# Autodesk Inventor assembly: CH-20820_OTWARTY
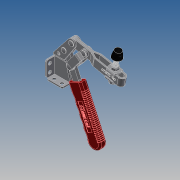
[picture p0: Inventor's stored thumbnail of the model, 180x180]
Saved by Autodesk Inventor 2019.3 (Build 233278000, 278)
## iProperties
Company: Î¢ÈíÖÐ¹ú
Created: 2011-12
Part Number: CH-20820_OTWARTY
Material: Ogólny
Description: STEP AP203
Document SubType Name: Assembly
Designer: CADENGINEERING4
Sending System: SolidWorks 2010
Preprocessor: SwSTEP 2.0
Title: CH-20820.STEP
Author: Î¢ÈíÓÃ»§
Revision Number: ÈÎºÎ
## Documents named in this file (10)
- E:\STRONA\Horizontal toggle clamp\CH-20820\CH-20820_OTWARTY.iam
- E:\STRONA\Horizontal toggle clamp\CH-20820\20820-02.ipt
- E:\STRONA\Horizontal toggle clamp\CH-20820\20820-06.ipt
- E:\STRONA\Horizontal toggle clamp\CH-20820\56212.ipt
- E:\STRONA\Horizontal toggle clamp\CH-20820\20820-03.ipt
- E:\STRONA\Horizontal toggle clamp\CH-20820\FW516.ipt
- E:\STRONA\Horizontal toggle clamp\CH-20820\20820-04.ipt
- E:\STRONA\Horizontal toggle clamp\CH-20820\CH-20820-05.ipt
- E:\STRONA\Horizontal toggle clamp\CH-20820\56212-02.ipt
- E:\STRONA\Horizontal toggle clamp\CH-20820\20820-01.ipt
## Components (15 placed, 15 different names)
1. 20820-02_1 — Zestawiające:1, Zestawiające:4, Zestawiające:6, Zestawiające:9, Zestawiające:24, Zestawiające:25, Zestawiające:28
2. 20820-06_2 — Zestawiające:22, Zestawiające:23
3. 56212_3 — Równoległe:1, Zestawiające:2, Zestawiające:5, Zestawiające:7, Zestawiające:9
4. 20820-06_4 — Zestawiające:28, Zestawiające:29, Zestawiające:30
5. 20820-03_5 — Zestawiające:10, Zestawiające:11, Zestawiające:12, Zestawiające:13, Zestawiające:14, Zestawiające:17, Zestawiające:18, Zestawiające:19, Zestawiające:20
6. FW516_6 — Równoległe:2, Zestawiające:5, Zestawiające:6, Zestawiające:8
7. 20820-04_7 — Zestawiające:19, Zestawiające:20, Zestawiające:21, Zestawiające:22, Zestawiające:23, Zestawiające:24, Zestawiające:25, Zestawiające:26, Zestawiające:27
8. CH-20820-05_8 — Zestawiające:10, Zestawiające:11, Zestawiające:12, Zestawiające:31
9. 56212-02_9 — Równoległe:1, Zestawiające:3
10. 20820-01_10 — Zestawiające:13, Zestawiające:14, Zestawiające:15, Zestawiające:16, Zestawiające:29, Zestawiające:30, Zestawiające:31
11. 20820-06_11 — Zestawiające:15, Zestawiające:16
12. 20820-06_12 — Zestawiające:26, Zestawiające:27
13. FW516_13 — Równoległe:2, Zestawiające:1, Zestawiające:2, Zestawiające:3, Zestawiające:4
14. 56212-02_14 — Zestawiające:7, Zestawiające:8
15. 20820-04_15 — Zestawiające:17, Zestawiające:18, Zestawiające:21
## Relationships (33: Mate 31, Flush 2)
- Równoległe:1 [Flush]: 56212_3 ↔ 56212-02_9
- Równoległe:2 [Flush]: FW516_6 ↔ FW516_13
- Zestawiające:1 [Mate]: 20820-02_1 ↔ FW516_13
- Zestawiające:2 [Mate]: 56212_3 ↔ FW516_13
- Zestawiające:3 [Mate]: 56212-02_9 ↔ FW516_13
- Zestawiające:4 [Mate]: 20820-02_1 ↔ FW516_13
- Zestawiające:5 [Mate]: 56212_3 ↔ FW516_6
- Zestawiające:6 [Mate]: 20820-02_1 ↔ FW516_6
- Zestawiające:7 [Mate]: 56212_3 ↔ 56212-02_14
- Zestawiające:8 [Mate]: FW516_6 ↔ 56212-02_14
- Zestawiające:9 [Mate]: 20820-02_1 ↔ 56212_3
- Zestawiające:10 [Mate]: 20820-03_5 ↔ CH-20820-05_8
- Zestawiające:11 [Mate]: 20820-03_5 ↔ CH-20820-05_8
- Zestawiające:12 [Mate]: 20820-03_5 ↔ CH-20820-05_8
- Zestawiające:13 [Mate]: 20820-03_5 ↔ 20820-01_10
- Zestawiające:14 [Mate]: 20820-03_5 ↔ 20820-01_10
- Zestawiające:15 [Mate]: 20820-01_10 ↔ 20820-06_11
- Zestawiające:16 [Mate]: 20820-01_10 ↔ 20820-06_11
- Zestawiające:17 [Mate]: 20820-03_5 ↔ 20820-04_15
- Zestawiające:18 [Mate]: 20820-03_5 ↔ 20820-04_15
- Zestawiające:19 [Mate]: 20820-03_5 ↔ 20820-04_7
- Zestawiające:20 [Mate]: 20820-03_5 ↔ 20820-04_7
- Zestawiające:21 [Mate]: 20820-04_7 ↔ 20820-04_15
- Zestawiające:22 [Mate]: 20820-06_2 ↔ 20820-04_7
- Zestawiające:23 [Mate]: 20820-06_2 ↔ 20820-04_7
- Zestawiające:24 [Mate]: 20820-02_1 ↔ 20820-04_7
- Zestawiające:25 [Mate]: 20820-02_1 ↔ 20820-04_7
- Zestawiające:26 [Mate]: 20820-04_7 ↔ 20820-06_12
- Zestawiające:27 [Mate]: 20820-04_7 ↔ 20820-06_12
- Zestawiające:28 [Mate]: 20820-02_1 ↔ 20820-06_4
- Zestawiające:29 [Mate]: 20820-06_4 ↔ 20820-01_10
- Zestawiające:30 [Mate]: 20820-06_4 ↔ 20820-01_10
- Zestawiające:31 [Mate]: CH-20820-05_8 ↔ 20820-01_10
